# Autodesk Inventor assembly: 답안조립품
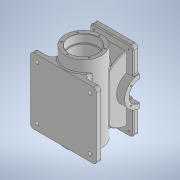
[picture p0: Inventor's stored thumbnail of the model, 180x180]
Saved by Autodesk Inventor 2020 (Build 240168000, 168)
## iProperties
Created: 2023-07
Part Number: 답안조립품
Document SubType Name: Assembly
Designer: oem
Author: oem
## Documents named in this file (2)
- C:\Users\oem\Desktop\730706V1012\답안조립품.iam
- C:\Users\oem\Desktop\730706V1012\본체.ipt
